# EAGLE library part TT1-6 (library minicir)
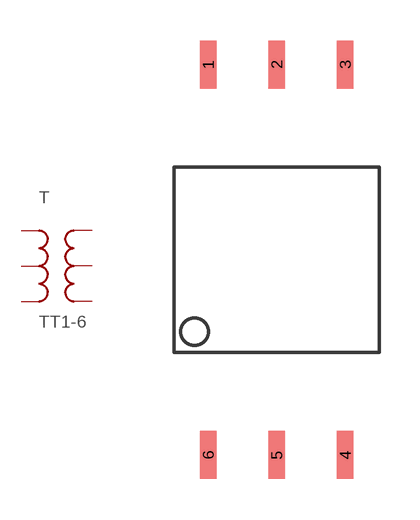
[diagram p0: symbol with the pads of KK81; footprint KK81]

Designator prefix T

## TT1-6  [KK81]
1  S2  pas
2  ST  pas
3  S1  pas
4  P1  pas
5  PT  pas
6  P2  pas

## Footprint KK81 (pad centres in mm)
smd 0.61 x 1.778: 1 -2.54,7.239; 2 0,7.239; 3 2.54,7.239; 4 2.54,-7.239; 5 0,-7.239; 6 -2.54,-7.239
